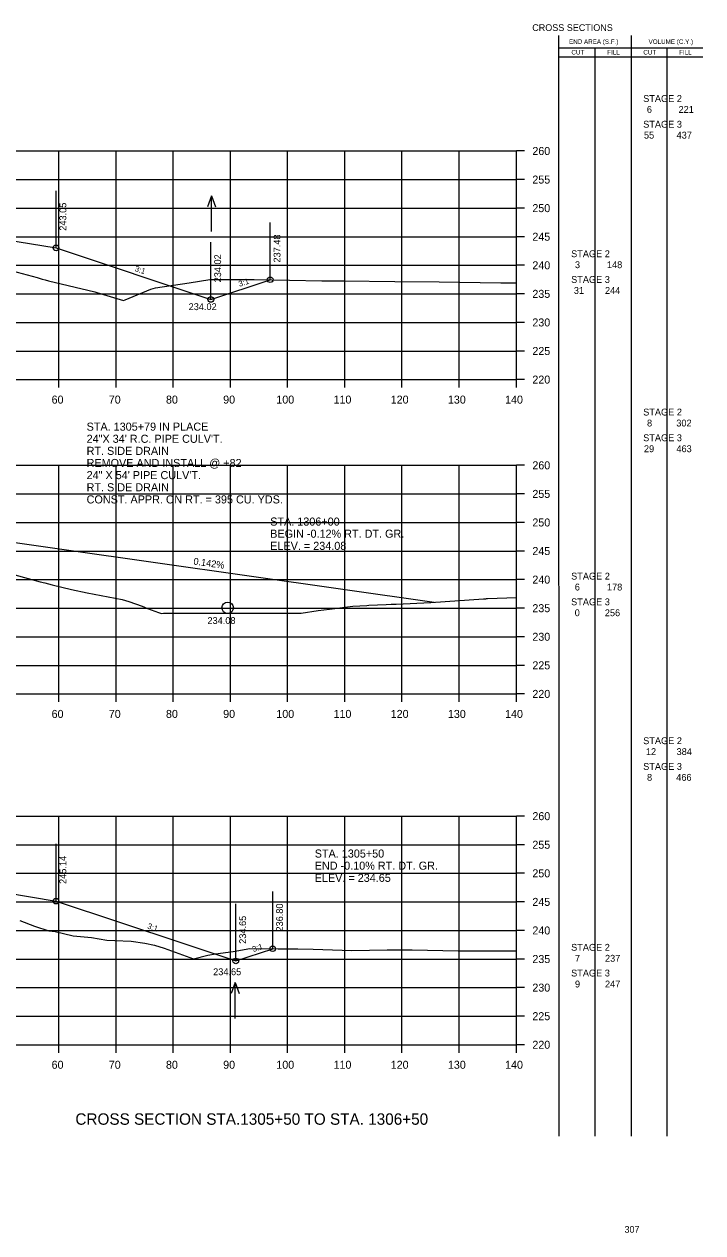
# Model space of a CAD drawing. Extents: x 1342547 to 1344156, y -1532351 to -1517216.
# Drawn here: x 1342756.8 to 1342875.5, y -1518710.4 to -1518498.9 of the extents above; entities that cross this region are included whole.
import ezdxf

# ---------------------------------------------------------------- set-up
doc = ezdxf.new("R2010")
doc.units = 0
for name, color, linetype in [('Level 2', 7, 'Continuous'), ('R_Axis', 7, 'Continuous'), ('R_Axis Annot', 7, 'Continuous'), ('R_Border Notes', 7, 'Continuous'), ('R_Draft', 7, 'Continuous'), ('R_Drive', 7, 'Continuous'), ('R_Exist Surface', 7, 'Continuous'), ('R_Fin Surface', 7, 'Continuous'), ('R_Grid', 7, 'Continuous'), ('R_No Plot', 7, 'Continuous'), ('R_Water', 7, 'Continuous'), ('R_Water Annot', 7, 'Continuous'), ('R_Xsect Elev', 7, 'Continuous'), ('R_Xsect Slope', 7, 'Continuous')]:
    doc.layers.add(name, color=color, linetype=linetype)

msp = doc.modelspace()

# ---------------------------------------------------------------- linework, layer by layer
at = {"layer": 'Level 2'}
for p, q in [((1342850.33, -1518693.52), (1342850.32, -1518500.91)), ((1342862.99, -1518693.52), (1342862.99, -1518500.91)), ((1342850.32, -1518503.07), (1342863.59, -1518503.07)), ((1342856.66, -1518693.52), (1342856.66, -1518503.07)), ((1342863.59, -1518503.07), (1342875.48, -1518503.07)), ((1342869.23, -1518693.52), (1342869.23, -1518503.07)), ((1342850.32, -1518504.64), (1342863.59, -1518504.64)), ((1342863.59, -1518504.64), (1342875.48, -1518504.64))]:
    msp.add_line(p, q, dxfattribs=at)
at = {"layer": 'R_Axis'}
for p, q in [((1342842.87, -1518561.13), (1342842.87, -1518521.13)), ((1342844.27, -1518521.13), (1342842.87, -1518521.13)), ((1342844.27, -1518526.13), (1342842.87, -1518526.13)), ((1342844.27, -1518531.13), (1342842.87, -1518531.13)), ((1342844.27, -1518536.13), (1342842.87, -1518536.13)), ((1342844.27, -1518541.13), (1342842.87, -1518541.13)), ((1342844.27, -1518546.13), (1342842.87, -1518546.13)), ((1342844.27, -1518551.13), (1342842.87, -1518551.13)), ((1342844.27, -1518556.13), (1342842.87, -1518556.13)), ((1342562.87, -1518561.13), (1342842.87, -1518561.13)), ((1342762.87, -1518562.53), (1342762.87, -1518561.13)), ((1342772.87, -1518562.53), (1342772.87, -1518561.13)), ((1342782.87, -1518562.53), (1342782.87, -1518561.13)), ((1342792.87, -1518562.53), (1342792.87, -1518561.13)), ((1342802.87, -1518562.53), (1342802.87, -1518561.13)), ((1342812.87, -1518562.53), (1342812.87, -1518561.13)), ((1342822.87, -1518562.53), (1342822.87, -1518561.13)), ((1342832.87, -1518562.53), (1342832.87, -1518561.13)), ((1342842.87, -1518562.53), (1342842.87, -1518561.13)), ((1342844.27, -1518561.13), (1342842.87, -1518561.13)), ((1342842.87, -1518616.13), (1342842.87, -1518576.13)), ((1342844.27, -1518576.13), (1342842.87, -1518576.13)), ((1342844.27, -1518581.13), (1342842.87, -1518581.13)), ((1342844.27, -1518586.13), (1342842.87, -1518586.13)), ((1342844.27, -1518591.13), (1342842.87, -1518591.13)), ((1342844.27, -1518596.13), (1342842.87, -1518596.13)), ((1342844.27, -1518601.13), (1342842.87, -1518601.13)), ((1342844.27, -1518606.13), (1342842.87, -1518606.13)), ((1342844.27, -1518611.13), (1342842.87, -1518611.13)), ((1342562.87, -1518616.13), (1342842.87, -1518616.13)), ((1342762.87, -1518617.53), (1342762.87, -1518616.13)), ((1342772.87, -1518617.53), (1342772.87, -1518616.13)), ((1342782.87, -1518617.53), (1342782.87, -1518616.13)), ((1342792.87, -1518617.53), (1342792.87, -1518616.13)), ((1342802.87, -1518617.53), (1342802.87, -1518616.13)), ((1342812.87, -1518617.53), (1342812.87, -1518616.13)), ((1342822.87, -1518617.53), (1342822.87, -1518616.13)), ((1342832.87, -1518617.53), (1342832.87, -1518616.13)), ((1342842.87, -1518617.53), (1342842.87, -1518616.13)), ((1342844.27, -1518616.13), (1342842.87, -1518616.13)), ((1342842.87, -1518677.52), (1342842.87, -1518637.52)), ((1342844.27, -1518637.52), (1342842.87, -1518637.52)), ((1342844.27, -1518642.52), (1342842.87, -1518642.52)), ((1342844.27, -1518647.52), (1342842.87, -1518647.52)), ((1342844.27, -1518652.52), (1342842.87, -1518652.52)), ((1342844.27, -1518657.52), (1342842.87, -1518657.52)), ((1342844.27, -1518662.52), (1342842.87, -1518662.52)), ((1342844.27, -1518667.52), (1342842.87, -1518667.52)), ((1342844.27, -1518672.52), (1342842.87, -1518672.52)), ((1342562.87, -1518677.52), (1342842.87, -1518677.52)), ((1342762.87, -1518678.92), (1342762.87, -1518677.52)), ((1342772.87, -1518678.92), (1342772.87, -1518677.52)), ((1342782.87, -1518678.92), (1342782.87, -1518677.52)), ((1342792.87, -1518678.92), (1342792.87, -1518677.52)), ((1342802.87, -1518678.92), (1342802.87, -1518677.52)), ((1342812.87, -1518678.92), (1342812.87, -1518677.52)), ((1342822.87, -1518678.92), (1342822.87, -1518677.52)), ((1342832.87, -1518678.92), (1342832.87, -1518677.52)), ((1342842.87, -1518678.92), (1342842.87, -1518677.52)), ((1342844.27, -1518677.52), (1342842.87, -1518677.52))]:
    msp.add_line(p, q, dxfattribs=at)
at = {"layer": 'R_Drive'}
msp.add_lwpolyline([(1342732.37, -1518588.99), (1342747.36, -1518588.53), (1342828.51, -1518600.07)], dxfattribs=at)
at = {"layer": 'R_Exist Surface'}
for points in [[(1342752.96, -1518541.61), (1342759.09, -1518543.28), (1342759.96, -1518543.55), (1342760.45, -1518543.68), (1342761.03, -1518543.83), (1342769.16, -1518545.79), (1342769.53, -1518545.87), (1342774.2, -1518547.27), (1342774.46, -1518547.18), (1342778.93, -1518545.33), (1342779.75, -1518545.08), (1342785.63, -1518544.17), (1342789.29, -1518543.63), (1342793.45, -1518543.59), (1342797.05, -1518543.59), (1342803.19, -1518543.72), (1342808.88, -1518543.86), (1342812.68, -1518543.83), (1342821.61, -1518543.94), (1342829.36, -1518544.02), (1342840.13, -1518544.21), (1342842.87, -1518544.22)], [(1342754.79, -1518595.2), (1342759.61, -1518596.53), (1342760.43, -1518596.72), (1342761.68, -1518597.05), (1342765.05, -1518597.85), (1342767.81, -1518598.47), (1342773.95, -1518599.62), (1342775.13, -1518599.93), (1342777.44, -1518600.76), (1342778.34, -1518601.17), (1342780.29, -1518601.88), (1342780.64, -1518601.99), (1342780.77, -1518602.07), (1342781.14, -1518602.02), (1342786.2, -1518602), (1342787.88, -1518601.98), (1342788.93, -1518601.98), (1342797.47, -1518601.98), (1342805.25, -1518601.99), (1342808.23, -1518601.53), (1342810.19, -1518601.28), (1342814.26, -1518600.76), (1342816.7, -1518600.64), (1342817.06, -1518600.62), (1342820.12, -1518600.46), (1342820.99, -1518600.44), (1342821.83, -1518600.4), (1342827.91, -1518600.11), (1342837.1, -1518599.49), (1342837.52, -1518599.47), (1342837.63, -1518599.46), (1342837.81, -1518599.44), (1342842.87, -1518599.27)], [(1342756.04, -1518655.8), (1342758.61, -1518656.78), (1342761.14, -1518657.56), (1342762.25, -1518657.7), (1342765.39, -1518658.45), (1342768.57, -1518658.78), (1342771.25, -1518659.21), (1342772.63, -1518659.27), (1342775.54, -1518659.37), (1342777.9, -1518659.77), (1342779.58, -1518660.11), (1342781.27, -1518660.59), (1342786.41, -1518662.46), (1342788.93, -1518661.85), (1342790.28, -1518661.63), (1342793.32, -1518661.22), (1342796.27, -1518660.7), (1342801.23, -1518660.72), (1342804.67, -1518660.74), (1342807.31, -1518660.81), (1342814.11, -1518661.02), (1342820.26, -1518660.93), (1342824.64, -1518660.92), (1342832.69, -1518661.09), (1342833.5, -1518661.11), (1342833.99, -1518661.11), (1342842.87, -1518661.08)]]:
    msp.add_lwpolyline(points, dxfattribs=at)
at = {"layer": 'R_Fin Surface'}
for points in [[(1342636.56, -1518544.28), (1342639.33, -1518545.2), (1342643.37, -1518543.86), (1342650.5, -1518542.67), (1342665.37, -1518540.19), (1342671.37, -1518539.73), (1342673.37, -1518539.58), (1342702.87, -1518537.3), (1342732.37, -1518535.03), (1342734.37, -1518534.88), (1342740.37, -1518534.42), (1342753.42, -1518536.59), (1342762.37, -1518538.08), (1342789.44, -1518547.11), (1342799.82, -1518543.65)], [(1342628.95, -1518660.12), (1342633.21, -1518661.54), (1342643.37, -1518658.16), (1342650.5, -1518656.97), (1342665.37, -1518654.49), (1342671.37, -1518654.03), (1342673.37, -1518653.87), (1342702.87, -1518651.6), (1342732.37, -1518649.33), (1342734.37, -1518649.18), (1342740.37, -1518648.71), (1342753.42, -1518650.89), (1342762.37, -1518652.38), (1342784.52, -1518659.77), (1342790.99, -1518661.92), (1342793.81, -1518662.86), (1342800.26, -1518660.71)]]:
    msp.add_lwpolyline(points, dxfattribs=at)
at = {"layer": 'R_Grid'}
for p, q in [((1342562.87, -1518521.13), (1342842.87, -1518521.13)), ((1342762.87, -1518561.13), (1342762.87, -1518521.13)), ((1342772.87, -1518561.13), (1342772.87, -1518521.13)), ((1342782.87, -1518561.13), (1342782.87, -1518521.13)), ((1342792.87, -1518561.13), (1342792.87, -1518521.13)), ((1342802.87, -1518561.13), (1342802.87, -1518521.13)), ((1342812.87, -1518561.13), (1342812.87, -1518521.13)), ((1342822.87, -1518561.13), (1342822.87, -1518521.13)), ((1342832.87, -1518561.13), (1342832.87, -1518521.13)), ((1342842.87, -1518561.13), (1342842.87, -1518521.13)), ((1342562.87, -1518526.13), (1342842.87, -1518526.13)), ((1342562.87, -1518531.13), (1342842.87, -1518531.13)), ((1342562.87, -1518536.13), (1342842.87, -1518536.13)), ((1342562.87, -1518541.13), (1342842.87, -1518541.13)), ((1342562.87, -1518546.13), (1342842.87, -1518546.13)), ((1342562.87, -1518551.13), (1342842.87, -1518551.13)), ((1342562.87, -1518556.13), (1342842.87, -1518556.13)), ((1342562.87, -1518561.13), (1342842.87, -1518561.13)), ((1342562.87, -1518576.13), (1342842.87, -1518576.13)), ((1342762.87, -1518616.13), (1342762.87, -1518576.13)), ((1342772.87, -1518616.13), (1342772.87, -1518576.13)), ((1342782.87, -1518616.13), (1342782.87, -1518576.13)), ((1342792.87, -1518616.13), (1342792.87, -1518576.13)), ((1342802.87, -1518616.13), (1342802.87, -1518576.13)), ((1342812.87, -1518616.13), (1342812.87, -1518576.13)), ((1342822.87, -1518616.13), (1342822.87, -1518576.13)), ((1342832.87, -1518616.13), (1342832.87, -1518576.13)), ((1342842.87, -1518616.13), (1342842.87, -1518576.13)), ((1342562.87, -1518581.13), (1342842.87, -1518581.13)), ((1342562.87, -1518586.13), (1342842.87, -1518586.13)), ((1342562.87, -1518591.13), (1342842.87, -1518591.13)), ((1342562.87, -1518596.13), (1342842.87, -1518596.13)), ((1342562.87, -1518601.13), (1342842.87, -1518601.13)), ((1342562.87, -1518606.13), (1342842.87, -1518606.13)), ((1342562.87, -1518611.13), (1342842.87, -1518611.13)), ((1342562.87, -1518616.13), (1342842.87, -1518616.13)), ((1342562.87, -1518637.52), (1342842.87, -1518637.52)), ((1342762.87, -1518677.52), (1342762.87, -1518637.52)), ((1342772.87, -1518677.52), (1342772.87, -1518637.52)), ((1342782.87, -1518677.52), (1342782.87, -1518637.52)), ((1342792.87, -1518677.52), (1342792.87, -1518637.52)), ((1342802.87, -1518677.52), (1342802.87, -1518637.52)), ((1342812.87, -1518677.52), (1342812.87, -1518637.52)), ((1342822.87, -1518677.52), (1342822.87, -1518637.52)), ((1342832.87, -1518677.52), (1342832.87, -1518637.52)), ((1342842.87, -1518677.52), (1342842.87, -1518637.52)), ((1342562.87, -1518642.52), (1342842.87, -1518642.52)), ((1342562.87, -1518647.52), (1342842.87, -1518647.52)), ((1342562.87, -1518652.52), (1342842.87, -1518652.52)), ((1342562.87, -1518657.52), (1342842.87, -1518657.52)), ((1342562.87, -1518662.52), (1342842.87, -1518662.52)), ((1342562.87, -1518667.52), (1342842.87, -1518667.52)), ((1342562.87, -1518672.52), (1342842.87, -1518672.52)), ((1342562.87, -1518677.52), (1342842.87, -1518677.52))]:
    msp.add_line(p, q, dxfattribs=at)
at = {"layer": 'R_No Plot'}
for centre in [(1342762.37, -1518538.08), (1342799.82, -1518543.65), (1342789.44, -1518547.11), (1342762.37, -1518652.38), (1342800.26, -1518660.71), (1342793.81, -1518662.86)]:
    msp.add_circle(centre, 0.5, dxfattribs=at)
at = {"layer": 'R_Water'}
for p, q in [((1342789.54, -1518528.96), (1342788.84, -1518530.88)), ((1342789.54, -1518535.24), (1342789.54, -1518528.96)), ((1342789.54, -1518528.96), (1342790.24, -1518530.88)), ((1342793.68, -1518666.63), (1342792.98, -1518668.56)), ((1342793.68, -1518672.92), (1342793.68, -1518666.63)), ((1342793.68, -1518666.63), (1342794.38, -1518668.56))]:
    msp.add_line(p, q, dxfattribs=at)
msp.add_circle((1342792.38, -1518601.05), 1, dxfattribs=at)
at = {"layer": 'R_Xsect Elev'}
for p, q in [((1342762.37, -1518538.08), (1342762.37, -1518528.08)), ((1342799.82, -1518543.65), (1342799.82, -1518533.65)), ((1342789.44, -1518547.11), (1342789.44, -1518537.11)), ((1342762.37, -1518652.38), (1342762.37, -1518642.38)), ((1342800.26, -1518660.71), (1342800.26, -1518650.71)), ((1342793.81, -1518662.86), (1342793.81, -1518652.86))]:
    msp.add_line(p, q, dxfattribs=at)

# ---------------------------------------------------------------- texts
at = {"layer": 'Level 2'}
for s, height, p in [('END AREA (S.F.)', 0.7937, (1342852.08, -1518502.39)), ('VOLUME (C.Y.)', 0.7937, (1342865.99, -1518502.39)), ('CUT', 0.794, (1342852.5, -1518504.25)), ('FILL', 0.794, (1342858.76, -1518504.25)), ('CUT', 0.794, (1342865.07, -1518504.25)), ('FILL', 0.794, (1342871.33, -1518504.25)), (' STAGE 2 ', 1.2, (1342864.6, -1518512.55)), ('6', 1.2, (1342865.69, -1518514.46)), ('221', 1.2, (1342871.23, -1518514.46)), (' STAGE 3 ', 1.2, (1342864.6, -1518517.05)), ('55', 1.2, (1342865.18, -1518518.96)), ('437', 1.2, (1342870.89, -1518518.96)), (' STAGE 2 ', 1.2, (1342852, -1518539.71)), ('3', 1.2, (1342853.12, -1518541.63)), ('148', 1.2, (1342858.71, -1518541.63)), (' STAGE 3 ', 1.2, (1342852, -1518544.21)), ('31', 1.2, (1342852.92, -1518546.13)), ('244', 1.2, (1342858.37, -1518546.13)), (' STAGE 2 ', 1.2, (1342864.6, -1518567.41)), ('8', 1.2, (1342865.72, -1518569.33)), ('302', 1.2, (1342870.84, -1518569.33)), (' STAGE 3 ', 1.2, (1342864.6, -1518571.91)), ('29', 1.2, (1342865.18, -1518573.83)), ('463', 1.2, (1342870.86, -1518573.83)), (' STAGE 2 ', 1.2, (1342852, -1518596.12)), ('6', 1.2, (1342853.09, -1518598.03)), ('178', 1.2, (1342858.71, -1518598.03)), (' STAGE 3 ', 1.2, (1342852, -1518600.62)), ('0', 1.2, (1342853.07, -1518602.53)), ('256', 1.2, (1342858.34, -1518602.53)), (' STAGE 2 ', 1.2, (1342864.6, -1518624.92)), ('12', 1.2, (1342865.52, -1518626.83)), ('384', 1.2, (1342870.89, -1518626.83)), (' STAGE 3 ', 1.2, (1342864.6, -1518629.42)), ('8', 1.2, (1342865.72, -1518631.33)), ('466', 1.2, (1342870.83, -1518631.33)), (' STAGE 2 ', 1.2, (1342852, -1518661.07)), ('7', 1.2, (1342853.12, -1518662.99)), ('237', 1.2, (1342858.37, -1518662.99)), (' STAGE 3 ', 1.2, (1342852, -1518665.57)), ('9', 1.2, (1342853.12, -1518667.49)), ('247', 1.2, (1342858.37, -1518667.49))]:
    msp.add_text(s, height=height, dxfattribs=at).set_placement(p)
at = {"layer": 'R_Axis Annot'}
for s, p in [('260', (1342845.67, -1518521.83)), ('255', (1342845.67, -1518526.83)), ('250', (1342845.67, -1518531.83)), ('245', (1342845.67, -1518536.83)), ('240', (1342845.67, -1518541.83)), ('235', (1342845.67, -1518546.83)), ('230', (1342845.67, -1518551.83)), ('225', (1342845.67, -1518556.83)), ('220', (1342845.67, -1518561.83)), ('60', (1342761.6, -1518565.33)), ('70', (1342771.6, -1518565.33)), ('80', (1342781.6, -1518565.33)), ('90', (1342791.6, -1518565.33)), ('100', (1342800.9, -1518565.33)), ('110', (1342810.9, -1518565.33)), ('120', (1342820.9, -1518565.33)), ('130', (1342830.9, -1518565.33)), ('140', (1342840.9, -1518565.33)), ('260', (1342845.67, -1518576.83)), ('255', (1342845.67, -1518581.83)), ('250', (1342845.67, -1518586.83)), ('245', (1342845.67, -1518591.83)), ('240', (1342845.67, -1518596.83)), ('235', (1342845.67, -1518601.83)), ('230', (1342845.67, -1518606.83)), ('225', (1342845.67, -1518611.83)), ('220', (1342845.67, -1518616.83)), ('60', (1342761.6, -1518620.33)), ('70', (1342771.6, -1518620.33)), ('80', (1342781.6, -1518620.33)), ('90', (1342791.6, -1518620.33)), ('100', (1342800.9, -1518620.33)), ('110', (1342810.9, -1518620.33)), ('120', (1342820.9, -1518620.33)), ('130', (1342830.9, -1518620.33)), ('140', (1342840.9, -1518620.33)), ('260', (1342845.67, -1518638.22)), ('255', (1342845.67, -1518643.22)), ('250', (1342845.67, -1518648.22)), ('245', (1342845.67, -1518653.22)), ('240', (1342845.67, -1518658.22)), ('235', (1342845.67, -1518663.22)), ('230', (1342845.67, -1518668.22)), ('225', (1342845.67, -1518673.22)), ('220', (1342845.67, -1518678.22)), ('60', (1342761.6, -1518681.72)), ('70', (1342771.6, -1518681.72)), ('80', (1342781.6, -1518681.72)), ('90', (1342791.6, -1518681.72)), ('100', (1342800.9, -1518681.72)), ('110', (1342810.9, -1518681.72)), ('120', (1342820.9, -1518681.72)), ('130', (1342830.9, -1518681.72)), ('140', (1342840.9, -1518681.72))]:
    msp.add_text(s, height=1.4, dxfattribs=at).set_placement(p)
at = {"layer": 'R_Border Notes'}
for s, height, p in [('CROSS SECTIONS', 1.1775, (1342845.65, -1518500.13)), ('STA. 1305+79 IN PLACE', 1.4147, (1342767.72, -1518570.07)), ('24"X 34\' R.C. PIPE CULV\'T.', 1.4147, (1342767.72, -1518572.19)), ('RT. SIDE DRAIN', 1.4147, (1342767.72, -1518574.31)), ('REMOVE AND INSTALL @ +82', 1.4147, (1342767.72, -1518576.43)), ('24" X 54\' PIPE CULV\'T.', 1.4147, (1342767.72, -1518578.55)), ('RT. SIDE DRAIN', 1.4147, (1342767.72, -1518580.68)), ('CONST. APPR. ON RT. = 395 CU. YDS.', 1.4147, (1342767.72, -1518582.8)), ('307', 1.178, (1342861.78, -1518710.41))]:
    msp.add_text(s, height=height, dxfattribs=at).set_placement(p)
at = {"layer": 'R_Draft'}
msp.add_text('CROSS SECTION STA.1305+50 TO STA. 1306+50', height=2, dxfattribs=at).set_placement((1342765.76, -1518691.52))
at = {"layer": 'R_Water Annot'}
for s, height, p in [('234.02', 1.2, (1342785.56, -1518548.97)), ('234.02', 1.2, (1342785.56, -1518548.97)), ('STA. 1306+00', 1.4147, (1342799.83, -1518586.68)), ('BEGIN -0.12% RT. DT. GR.', 1.4147, (1342799.83, -1518588.8)), ('ELEV. = 234.08', 1.4147, (1342799.83, -1518590.93)), ('234.08', 1.2, (1342788.85, -1518603.89)), ('234.08', 1.2, (1342788.85, -1518603.89)), ('STA. 1305+50', 1.4147, (1342807.61, -1518644.77)), ('END -0.10% RT. DT. GR.', 1.4147, (1342807.61, -1518646.89)), ('ELEV. = 234.65', 1.4147, (1342807.61, -1518649.02))]:
    msp.add_text(s, height=height, dxfattribs=at).set_placement(p)
at = {"layer": 'R_Xsect Elev'}
for s, rotation, p in [('243.05', 90, (1342764.17, -1518535.08)), ('237.48', 90, (1342801.62, -1518540.65)), ('234.02', 90, (1342791.24, -1518544.11)), ('0.142%', 351.9029, (1342786.34, -1518593.47)), ('245.14', 90, (1342764.17, -1518649.38)), ('236.80', 90, (1342802.06, -1518657.71)), ('234.65', 90, (1342795.61, -1518659.86))]:
    msp.add_text(s, height=1.2, rotation=rotation, dxfattribs=at).set_placement(p)
msp.add_text('234.65', height=1.2, dxfattribs=at).set_placement((1342789.85, -1518665.35))
at = {"layer": 'R_Xsect Slope'}
for rotation, p in [(341.5651, (1342776.06, -1518542.12)), (18.4349, (1342794.47, -1518544.9)), (341.5651, (1342778.25, -1518657.15)), (18.4349, (1342796.88, -1518661.31))]:
    msp.add_text('3:1', height=1, rotation=rotation, dxfattribs=at).set_placement(p)

doc.saveas('drawing.dxf')
